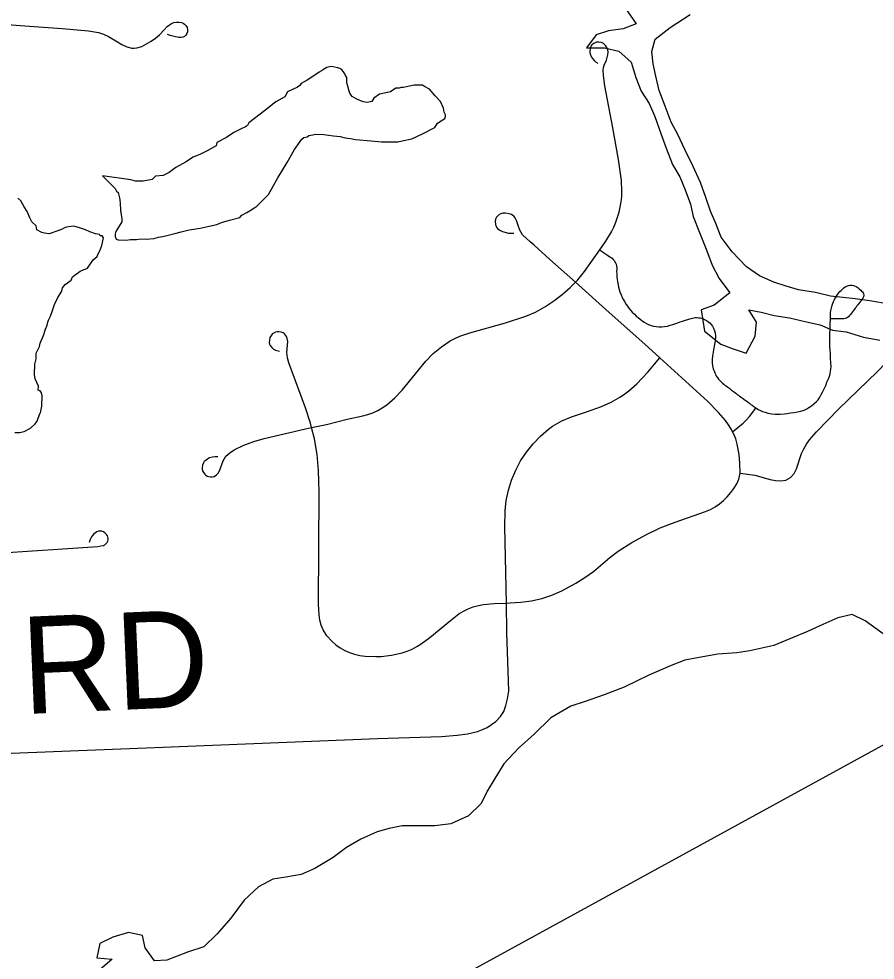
# Model space of a CAD drawing. Extents: x 0 to 34, y 0 to 22.
# Drawn here: x 6.2117 to 6.4623, y 19.1628 to 19.4382 of the extents above; entities that cross this region are included whole.
import ezdxf

# ---------------------------------------------------------------- set-up
doc = ezdxf.new("R2010")
doc.units = 0
for name, color, linetype in [('GM_X_Corporation', 7, 'Continuous'), ('GM_X_Minor_River', 7, 'Continuous'), ('GM_X_Township_Road', 7, 'Continuous'), ('GM_X_Township_Road_Text', 7, 'Continuous')]:
    doc.layers.add(name, color=color, linetype=linetype)

msp = doc.modelspace()

# ---------------------------------------------------------------- linework, layer by layer
at = {"layer": 'GM_X_Corporation'}
msp.add_lwpolyline([(6.02093, 18.98289), (6.47248, 19.23007), (6.55287, 19.2304), (6.5506, 19.34193), (6.52687, 19.36184), (6.5229, 19.4692), (6.42525, 19.4768), (6.41702, 19.54004), (6.41272, 19.59919), (6.66443, 19.85526), (6.74265, 19.90025)], dxfattribs=at)
at = {"layer": 'GM_X_Minor_River'}
for points in [[(6.38968, 19.44059), (6.39236, 19.4368), (6.38857, 19.43526), (6.38421, 19.43467), (6.38061, 19.43351), (6.37778, 19.4297), (6.38309, 19.42972), (6.38727, 19.42879), (6.3909, 19.42558), (6.39225, 19.42102), (6.39379, 19.41704), (6.39609, 19.41343), (6.39781, 19.40964), (6.39955, 19.40471), (6.40109, 19.40034), (6.40301, 19.3956), (6.40512, 19.392), (6.40665, 19.3882), (6.4082, 19.38403), (6.40897, 19.38042), (6.4109, 19.37568), (6.41301, 19.37036), (6.41455, 19.36619), (6.41666, 19.36221), (6.41972, 19.35804), (6.41518, 19.35441), (6.41139, 19.35306), (6.41237, 19.34679), (6.41714, 19.34301), (6.42075, 19.3417), (6.42455, 19.34039), (6.42719, 19.34534), (6.42755, 19.34952), (6.42525, 19.35312), (6.42886, 19.35238), (6.43266, 19.35145), (6.43722, 19.35071), (6.44216, 19.34959), (6.44615, 19.34866), (6.44977, 19.34716), (6.45376, 19.34661), (6.45889, 19.34511), (6.46364, 19.34418)], [(6.46567, 19.35484), (6.4613, 19.35558), (6.45636, 19.35631), (6.44915, 19.35704), (6.44477, 19.35816), (6.43984, 19.3589), (6.43622, 19.36002), (6.43261, 19.36114), (6.42843, 19.36302), (6.42461, 19.36567), (6.42042, 19.37002), (6.41717, 19.37438), (6.41563, 19.37836), (6.41409, 19.38196), (6.41274, 19.38595), (6.4112, 19.39032), (6.4089, 19.39525), (6.40659, 19.39999), (6.40448, 19.40435), (6.40257, 19.40795), (6.40083, 19.4127), (6.3991, 19.41725), (6.39813, 19.42143), (6.39735, 19.42504), (6.39696, 19.42865), (6.39789, 19.43226), (6.40223, 19.43571), (6.4081, 19.43953)], [(6.30729, 19.4216), (6.30711, 19.42217), (6.30673, 19.42275), (6.30617, 19.42332), (6.30561, 19.42371), (6.30504, 19.42391), (6.30316, 19.42432), (6.30258, 19.42413), (6.30182, 19.42396), (6.30087, 19.4234), (6.30029, 19.42303), (6.29953, 19.42266), (6.298, 19.42154), (6.29608, 19.42024), (6.29436, 19.41931), (6.29397, 19.41875), (6.29321, 19.41819), (6.29034, 19.4169), (6.28956, 19.41539), (6.28689, 19.41391), (6.28363, 19.4113), (6.27902, 19.40775), (6.27863, 19.407), (6.27806, 19.40663), (6.27672, 19.40607), (6.27462, 19.40497), (6.27251, 19.40348), (6.26965, 19.402), (6.26945, 19.40105), (6.26677, 19.39957), (6.26486, 19.39864), (6.26276, 19.39773), (6.26046, 19.39624), (6.2576, 19.39476), (6.25568, 19.39327), (6.25454, 19.39271), (6.25396, 19.39234), (6.25168, 19.39218), (6.25072, 19.39125), (6.24806, 19.39071), (6.24635, 19.39074), (6.24579, 19.39075), (6.24446, 19.39115), (6.23622, 19.39233)], [(6.23622, 19.39233), (6.23988, 19.38855), (6.24024, 19.38779), (6.24081, 19.3874), (6.24116, 19.38587), (6.24133, 19.38435), (6.24149, 19.38207), (6.24183, 19.37979), (6.24182, 19.37884), (6.24007, 19.37601), (6.23987, 19.37526), (6.23986, 19.3745), (6.24023, 19.37373), (6.24079, 19.37354), (6.24307, 19.3735), (6.2444, 19.37367), (6.2461, 19.37365), (6.24743, 19.37382), (6.24895, 19.3738), (6.25123, 19.37396), (6.25256, 19.37432), (6.2537, 19.37449), (6.25503, 19.37485), (6.25731, 19.37539), (6.25922, 19.37593), (6.2615, 19.37647), (6.26473, 19.377), (6.26739, 19.37753), (6.26968, 19.37806), (6.27101, 19.37862), (6.2733, 19.37934), (6.27634, 19.38006), (6.27692, 19.38081), (6.27845, 19.38155), (6.27941, 19.38211), (6.28075, 19.38304), (6.28132, 19.38341), (6.28478, 19.38678), (6.28751, 19.39168), (6.29023, 19.3962), (6.29237, 19.39997), (6.2945, 19.40298), (6.29508, 19.40354), (6.29603, 19.40371), (6.2966, 19.40409), (6.29774, 19.40426), (6.2985, 19.40444), (6.30097, 19.4044), (6.30229, 19.4042), (6.3038, 19.40398), (6.3057, 19.40377), (6.30721, 19.40337), (6.30872, 19.40316), (6.31024, 19.40294), (6.31478, 19.4025), (6.31781, 19.40227), (6.32255, 19.4022), (6.32388, 19.40256), (6.32673, 19.40309), (6.32979, 19.40457), (6.33342, 19.40642), (6.3342, 19.40773), (6.3363, 19.40903), (6.3365, 19.4096), (6.33651, 19.41017), (6.33614, 19.41094), (6.33597, 19.41208), (6.33505, 19.41399), (6.33355, 19.41572), (6.33188, 19.41764), (6.33037, 19.41843), (6.32981, 19.41881), (6.32734, 19.41885), (6.32601, 19.41849), (6.3243, 19.41813), (6.32354, 19.41814), (6.32297, 19.41796), (6.32202, 19.41797), (6.32049, 19.41685), (6.31725, 19.41614), (6.31553, 19.41502), (6.31495, 19.41408), (6.31362, 19.41372), (6.31248, 19.41393), (6.3106, 19.41471), (6.30928, 19.41549), (6.30891, 19.41588), (6.30854, 19.41645), (6.30836, 19.41703), (6.308, 19.41855), (6.30764, 19.4195), (6.30766, 19.42102), (6.30729, 19.4216)], [(6.21058, 19.31717), (6.21191, 19.31716), (6.21324, 19.31752), (6.21515, 19.31844), (6.21649, 19.31975), (6.21707, 19.3205), (6.21786, 19.32277), (6.21806, 19.32296), (6.21846, 19.32485), (6.21851, 19.32789), (6.21833, 19.32884), (6.21796, 19.32941), (6.2174, 19.32961), (6.21741, 19.33075), (6.2165, 19.33285), (6.21633, 19.33419), (6.21637, 19.33722), (6.21677, 19.33874), (6.2168, 19.34045), (6.21777, 19.34233), (6.21798, 19.34328), (6.21896, 19.34554), (6.21955, 19.34743), (6.21995, 19.34857), (6.22015, 19.34952), (6.22035, 19.35008), (6.22094, 19.35121), (6.22153, 19.35291), (6.22212, 19.35461), (6.2231, 19.35669), (6.22427, 19.35857), (6.22447, 19.35952), (6.22524, 19.36046), (6.22697, 19.36176), (6.22736, 19.36271), (6.22966, 19.36439), (6.23176, 19.3653), (6.2335, 19.36775), (6.23465, 19.36868), (6.23485, 19.36925), (6.23544, 19.37038), (6.23603, 19.37189), (6.23644, 19.37417), (6.23607, 19.37474), (6.2355, 19.37475), (6.23532, 19.37513), (6.23418, 19.37534), (6.23248, 19.37593), (6.23117, 19.37652), (6.22947, 19.37711), (6.22777, 19.37752), (6.22625, 19.37735), (6.2253, 19.37717), (6.22415, 19.37662), (6.22282, 19.37607), (6.22053, 19.37534), (6.21921, 19.37555), (6.21845, 19.37575), (6.21695, 19.37653), (6.21677, 19.37767), (6.21546, 19.37883), (6.21491, 19.37998), (6.21418, 19.38189), (6.21325, 19.38323), (6.21233, 19.38495), (6.21139, 19.38572)], [(6.46465, 19.25827), (6.45931, 19.26205), (6.45551, 19.26393), (6.45134, 19.26296), (6.44698, 19.26104), (6.44244, 19.25893), (6.43732, 19.25681), (6.43259, 19.25489), (6.42557, 19.25333), (6.42178, 19.25275), (6.41627, 19.25234), (6.41077, 19.25136), (6.4066, 19.25058), (6.40262, 19.24904), (6.39599, 19.24616), (6.3888, 19.24271), (6.38292, 19.2404), (6.37743, 19.23847), (6.37326, 19.23712), (6.36739, 19.23367), (6.36248, 19.2289), (6.35795, 19.22488), (6.3536, 19.2203), (6.35097, 19.21592), (6.34871, 19.21229), (6.34702, 19.20868), (6.34324, 19.20505), (6.33813, 19.20274), (6.33338, 19.20215), (6.32389, 19.2021), (6.3201, 19.20132), (6.3165, 19.20036), (6.31176, 19.19824), (6.3076, 19.19575), (6.30363, 19.19288), (6.29833, 19.18963), (6.29435, 19.1879), (6.2898, 19.18712), (6.28601, 19.18653), (6.28184, 19.18423), (6.27768, 19.18041), (6.27373, 19.17507), (6.26976, 19.17049), (6.2658, 19.16667), (6.26106, 19.16512), (6.25499, 19.16281), (6.25139, 19.16261), (6.24871, 19.1664), (6.24793, 19.17), (6.24375, 19.17093), (6.2392, 19.16958), (6.23542, 19.16766), (6.23449, 19.16348), (6.23905, 19.16312), (6.23546, 19.16006)], [(6.46465, 19.25827), (6.45931, 19.26205), (6.45551, 19.26393), (6.45134, 19.26296), (6.44698, 19.26104), (6.44244, 19.25893), (6.43732, 19.25681), (6.43259, 19.25489), (6.42557, 19.25333), (6.42178, 19.25275), (6.41627, 19.25234), (6.41077, 19.25136), (6.4066, 19.25058), (6.40262, 19.24904), (6.39599, 19.24616), (6.3888, 19.24271), (6.38292, 19.2404), (6.37743, 19.23847), (6.37326, 19.23712), (6.36739, 19.23367), (6.36248, 19.2289), (6.35795, 19.22488), (6.3536, 19.2203), (6.35097, 19.21592), (6.34871, 19.21229), (6.34702, 19.20868), (6.34324, 19.20505), (6.33813, 19.20274), (6.33338, 19.20215), (6.32389, 19.2021), (6.3201, 19.20132), (6.3165, 19.20036), (6.31176, 19.19824), (6.3076, 19.19575), (6.30363, 19.19288), (6.29833, 19.18963), (6.29435, 19.1879), (6.2898, 19.18712), (6.28601, 19.18653), (6.28184, 19.18423), (6.27768, 19.18041), (6.27373, 19.17507), (6.26976, 19.17049), (6.2658, 19.16667), (6.26106, 19.16512), (6.25499, 19.16281), (6.25139, 19.16261), (6.24871, 19.1664), (6.24793, 19.17), (6.24375, 19.17093), (6.2392, 19.16958), (6.23542, 19.16766), (6.23449, 19.16348), (6.23905, 19.16312), (6.23546, 19.16006)]]:
    msp.add_lwpolyline(points, dxfattribs=at)
at = {"layer": 'GM_X_Township_Road'}
for points in [[(6.2059, 19.43679), (6.21206, 19.43628), (6.2244, 19.43541), (6.23204, 19.43473), (6.23502, 19.43424), (6.23649, 19.43374), (6.23789, 19.43309), (6.24055, 19.43151), (6.24188, 19.43067), (6.24328, 19.42998), (6.24474, 19.42961), (6.24543, 19.42959), (6.24623, 19.4297), (6.24766, 19.43017), (6.24905, 19.43087), (6.2504, 19.43166), (6.25167, 19.43255), (6.25286, 19.43354), (6.2542, 19.43496), (6.25512, 19.43596), (6.25574, 19.43648), (6.25636, 19.43684), (6.25708, 19.43712), (6.25788, 19.43725), (6.2585, 19.43725), (6.25925, 19.43712), (6.25974, 19.43692), (6.26018, 19.43663), (6.26062, 19.43619), (6.26093, 19.43573), (6.26108, 19.43514), (6.26106, 19.43439), (6.26088, 19.43392), (6.26054, 19.43343), (6.26018, 19.43307), (6.25974, 19.43284), (6.2592, 19.43274), (6.25855, 19.43271), (6.2575, 19.43292), (6.25598, 19.43333), (6.25518, 19.43367)], [(6.38167, 19.37065), (6.38346, 19.37321), (6.38508, 19.37587), (6.38579, 19.37726), (6.3864, 19.37869), (6.38734, 19.38166), (6.38795, 19.38472), (6.38812, 19.38627), (6.38818, 19.38783), (6.38804, 19.39094), (6.38713, 19.39711), (6.38551, 19.40633), (6.38319, 19.41862), (6.38273, 19.42168), (6.38268, 19.42321), (6.38277, 19.42398), (6.38296, 19.42471), (6.38363, 19.42614), (6.38388, 19.42692), (6.38408, 19.42766), (6.38414, 19.42847), (6.38403, 19.42916), (6.38379, 19.42986), (6.38338, 19.43046), (6.38277, 19.43102), (6.38221, 19.43128), (6.38142, 19.4314), (6.3807, 19.43135), (6.37994, 19.43102), (6.37938, 19.43059), (6.37909, 19.43019), (6.37892, 19.42976), (6.37876, 19.42897), (6.37878, 19.42836), (6.37892, 19.42768), (6.37923, 19.42705), (6.37953, 19.42657), (6.38007, 19.426), (6.38048, 19.42564), (6.38109, 19.42526)], [(6.37457, 19.36117), (6.36711, 19.3678), (6.36253, 19.37197), (6.36134, 19.37296), (6.35909, 19.37507), (6.35864, 19.37573), (6.35831, 19.37634), (6.35777, 19.37777), (6.35733, 19.37925), (6.35697, 19.37998), (6.35652, 19.38048), (6.35584, 19.38096), (6.35517, 19.38118), (6.35414, 19.38138), (6.35336, 19.38133), (6.35276, 19.38118), (6.35226, 19.38096), (6.35183, 19.38063), (6.35146, 19.38023), (6.35118, 19.37963), (6.35108, 19.37888), (6.35118, 19.37803), (6.35151, 19.37725), (6.35178, 19.3769), (6.35216, 19.37655), (6.35261, 19.37625), (6.35321, 19.376), (6.35494, 19.37553), (6.35584, 19.37547), (6.35649, 19.37555)], [(6.37457, 19.36117), (6.37523, 19.36185), (6.3772, 19.36426), (6.38167, 19.37065)], [(6.38167, 19.37065), (6.38218, 19.37029), (6.3831, 19.36965), (6.38393, 19.3691), (6.38463, 19.36862), (6.38497, 19.36839), (6.3853, 19.36815), (6.38563, 19.3678), (6.38589, 19.36752), (6.38629, 19.36682), (6.38647, 19.3664), (6.38661, 19.36583), (6.38665, 19.36539), (6.38664, 19.36486), (6.38662, 19.36437), (6.38663, 19.36365), (6.38666, 19.36284), (6.38676, 19.36193), (6.38683, 19.36139), (6.38703, 19.3604), (6.38719, 19.35972), (6.38738, 19.35904), (6.38759, 19.35838), (6.38794, 19.35747), (6.38827, 19.35673), (6.38863, 19.356), (6.38894, 19.35549), (6.38941, 19.35467), (6.38976, 19.35416), (6.39021, 19.35356), (6.39065, 19.35299), (6.39116, 19.35243), (6.3918, 19.35177), (6.39236, 19.35124), (6.39289, 19.35079), (6.3935, 19.35031), (6.39395, 19.34998), (6.39465, 19.34951), (6.39533, 19.34911), (6.39594, 19.34881), (6.39668, 19.34852), (6.39737, 19.34833), (6.39814, 19.34818), (6.399, 19.34811), (6.39984, 19.34808), (6.40063, 19.34818), (6.40145, 19.34832), (6.40224, 19.34856), (6.40302, 19.34881), (6.40369, 19.34903), (6.40425, 19.34922), (6.40522, 19.34955), (6.40585, 19.34975), (6.40643, 19.34995), (6.40708, 19.35017), (6.40747, 19.35029), (6.40805, 19.35049), (6.4084, 19.35059), (6.40922, 19.35077), (6.40961, 19.35081), (6.41, 19.35083), (6.41059, 19.35078), (6.4111, 19.3507), (6.4118, 19.35051), (6.41232, 19.3503), (6.41288, 19.34999), (6.41325, 19.34975), (6.41359, 19.34949), (6.41396, 19.34915), (6.41427, 19.34881), (6.41462, 19.34829), (6.41496, 19.34775), (6.41526, 19.34698), (6.41542, 19.34639), (6.41548, 19.34602), (6.41553, 19.34565), (6.41554, 19.34525), (6.41555, 19.34485), (6.41549, 19.34444), (6.41541, 19.34387), (6.41526, 19.34308), (6.41516, 19.34239), (6.41507, 19.34187), (6.41499, 19.34139), (6.41487, 19.34072), (6.41478, 19.34013), (6.41471, 19.33972), (6.41466, 19.33935), (6.4146, 19.33884), (6.41458, 19.33839), (6.41458, 19.33807), (6.4146, 19.33746), (6.41468, 19.33684), (6.41478, 19.33633), (6.4149, 19.3358), (6.41502, 19.33542), (6.41522, 19.33491), (6.41534, 19.33461), (6.41551, 19.33424), (6.41568, 19.3339), (6.41594, 19.3335), (6.41614, 19.33324), (6.41644, 19.3328), (6.41667, 19.33252), (6.41696, 19.33223), (6.41729, 19.33188), (6.41757, 19.33164), (6.41796, 19.33132), (6.41838, 19.33099), (6.41867, 19.3308), (6.41914, 19.33044), (6.41971, 19.33002), (6.42027, 19.3296), (6.42056, 19.32939), (6.42107, 19.329), (6.42153, 19.32866), (6.42193, 19.32835), (6.42227, 19.32811), (6.42261, 19.32787), (6.42301, 19.32757), (6.42334, 19.32732), (6.42381, 19.32696), (6.42423, 19.32667), (6.4247, 19.32633), (6.42517, 19.32597), (6.42546, 19.32573), (6.42589, 19.32543), (6.42623, 19.32516), (6.42676, 19.32479), (6.42736, 19.32436)], [(6.29737, 19.31863), (6.30173, 19.31954), (6.30775, 19.32111), (6.31233, 19.32204), (6.31384, 19.32244), (6.31531, 19.32296), (6.31671, 19.32362), (6.31805, 19.32442), (6.31933, 19.32531), (6.32169, 19.32734), (6.32385, 19.3296), (6.33079, 19.33802), (6.33296, 19.34026), (6.33536, 19.34225), (6.33795, 19.34399), (6.33931, 19.34474), (6.34073, 19.34538), (6.34369, 19.34637), (6.35413, 19.34928), (6.36004, 19.35119), (6.3629, 19.35243), (6.36562, 19.35396), (6.36822, 19.35567), (6.3707, 19.35756), (6.37305, 19.35962), (6.37457, 19.36117)], [(6.39926, 19.33906), (6.39488, 19.34307), (6.38447, 19.35234), (6.37457, 19.36117)], [(6.44916, 19.35043), (6.44918, 19.35127), (6.44924, 19.3523), (6.4494, 19.35326), (6.44959, 19.35409), (6.44979, 19.35475), (6.44998, 19.35527), (6.45016, 19.35569), (6.45039, 19.35613), (6.45065, 19.35663), (6.45094, 19.35709), (6.45127, 19.35756), (6.45165, 19.35804), (6.45197, 19.35842), (6.45231, 19.35878), (6.45274, 19.35917), (6.45314, 19.35954), (6.45348, 19.35977), (6.4538, 19.35995), (6.45412, 19.3601), (6.45445, 19.36019), (6.45495, 19.36028), (6.45552, 19.36026), (6.45588, 19.3602), (6.45625, 19.36009), (6.4567, 19.35991), (6.457, 19.35973), (6.45727, 19.35952), (6.45758, 19.35924), (6.45802, 19.35882), (6.4583, 19.35856), (6.45853, 19.35833), (6.45875, 19.35808), (6.45889, 19.3578), (6.45897, 19.35733), (6.45889, 19.35688), (6.45867, 19.35651), (6.45837, 19.35611), (6.45807, 19.35572), (6.45779, 19.35536), (6.45749, 19.35496), (6.45715, 19.35452), (6.45694, 19.35425), (6.45668, 19.3539), (6.45642, 19.35357), (6.45617, 19.35325), (6.45591, 19.3529), (6.4556, 19.3525), (6.45531, 19.35211), (6.455, 19.3517), (6.45477, 19.35141), (6.45441, 19.35101), (6.45415, 19.35081), (6.45388, 19.35066), (6.45348, 19.35052), (6.45312, 19.35046), (6.45273, 19.35046), (6.45221, 19.35045), (6.45176, 19.35045), (6.45123, 19.35045), (6.45081, 19.35044), (6.45016, 19.35043), (6.44954, 19.35043), (6.44916, 19.35043)], [(6.42736, 19.32436), (6.42804, 19.32396), (6.42867, 19.32366), (6.42931, 19.32337), (6.43006, 19.3231), (6.43083, 19.32286), (6.43206, 19.32265), (6.43299, 19.32256), (6.43376, 19.32255), (6.43446, 19.32256), (6.43561, 19.32265), (6.43653, 19.32276), (6.43747, 19.3229), (6.43843, 19.32301), (6.43958, 19.32324), (6.44051, 19.32344), (6.44153, 19.32375), (6.44229, 19.32413), (6.44289, 19.32451), (6.44364, 19.32497), (6.44436, 19.32558), (6.44508, 19.32624), (6.44554, 19.32679), (6.44605, 19.32755), (6.44647, 19.32831), (6.44682, 19.32895), (6.44714, 19.32959), (6.44749, 19.33034), (6.44778, 19.33098), (6.44816, 19.33187), (6.44851, 19.33267), (6.44879, 19.33342), (6.44907, 19.33433), (6.44923, 19.33511), (6.44932, 19.33573), (6.44936, 19.33647), (6.4493, 19.33745), (6.44922, 19.33899), (6.44917, 19.34023), (6.44909, 19.34134), (6.44902, 19.34222), (6.44897, 19.34316), (6.44897, 19.3448), (6.44901, 19.34609), (6.4491, 19.34751), (6.44909, 19.34825), (6.44907, 19.34876), (6.44916, 19.35043)], [(6.29737, 19.31863), (6.29705, 19.31993), (6.29562, 19.3244), (6.29069, 19.33757), (6.29029, 19.33906), (6.29014, 19.3406), (6.29038, 19.34378), (6.29022, 19.34467), (6.29002, 19.34525), (6.28957, 19.34593), (6.28934, 19.34614), (6.28908, 19.34631), (6.28845, 19.34655), (6.2878, 19.34667), (6.28727, 19.34665), (6.28678, 19.34653), (6.28611, 19.34617), (6.28585, 19.34595), (6.2856, 19.34565), (6.28519, 19.34498), (6.28502, 19.34423), (6.28499, 19.34348), (6.28507, 19.34307), (6.28525, 19.34265), (6.28569, 19.34205), (6.2862, 19.34158), (6.28676, 19.34131), (6.28799, 19.341)], [(6.35435, 19.2673), (6.35393, 19.2896), (6.35397, 19.29424), (6.35427, 19.29732), (6.35493, 19.30034), (6.35589, 19.30328), (6.35708, 19.30614), (6.35853, 19.30887), (6.36022, 19.31146), (6.36216, 19.31386), (6.36432, 19.31608), (6.36665, 19.31812), (6.36789, 19.31904), (6.3692, 19.31985), (6.37058, 19.32057), (6.37343, 19.32175), (6.37783, 19.32324), (6.38219, 19.32481), (6.38502, 19.32608), (6.38772, 19.32759), (6.38899, 19.32846), (6.39022, 19.3294), (6.39252, 19.33147), (6.39573, 19.33482), (6.3977, 19.3372), (6.39926, 19.33906)], [(6.42055, 19.3174), (6.42019, 19.31811), (6.41938, 19.31942), (6.41847, 19.32068), (6.41645, 19.32303), (6.41316, 19.32631), (6.39926, 19.33906)], [(6.42275, 19.30527), (6.42701, 19.30473), (6.43158, 19.30348), (6.43312, 19.30315), (6.43465, 19.30302), (6.43617, 19.30328), (6.43751, 19.30407), (6.43856, 19.3052), (6.43929, 19.30656), (6.44074, 19.31101), (6.44137, 19.31243), (6.44214, 19.31378), (6.44304, 19.31505), (6.44506, 19.31741), (6.4516, 19.32409), (6.4628, 19.33491), (6.46555, 19.33779)], [(6.42055, 19.3174), (6.42365, 19.31991), (6.42451, 19.32083), (6.42547, 19.32185), (6.42672, 19.3235), (6.42736, 19.32436)], [(6.26989, 19.31003), (6.26909, 19.31004), (6.26833, 19.30996), (6.2675, 19.30975), (6.26686, 19.30942), (6.26618, 19.30894), (6.26595, 19.30867), (6.26569, 19.30827), (6.26545, 19.30761), (6.26532, 19.30688), (6.26534, 19.30648), (6.26547, 19.30595), (6.26571, 19.30545), (6.26609, 19.30496), (6.26642, 19.30467), (6.26681, 19.30446), (6.26728, 19.30427), (6.26774, 19.3042), (6.26827, 19.30422), (6.26885, 19.30436), (6.26957, 19.3048), (6.27, 19.30526), (6.27042, 19.30597), (6.27148, 19.30895), (6.2723, 19.31023), (6.2734, 19.31127), (6.27473, 19.31209), (6.27755, 19.31345), (6.28046, 19.31457), (6.28345, 19.31545), (6.29561, 19.31824), (6.29737, 19.31863)], [(6.30326, 19.25613), (6.30182, 19.25771), (6.30077, 19.25946), (6.3002, 19.26082), (6.29976, 19.26232), (6.29953, 19.26386), (6.29942, 19.26698), (6.29954, 19.29987), (6.2994, 19.30609), (6.29895, 19.31075), (6.29817, 19.31537), (6.29737, 19.31863)], [(6.42275, 19.30527), (6.42269, 19.30819), (6.42249, 19.31077), (6.4219, 19.31381), (6.42146, 19.31529), (6.42089, 19.31673), (6.42055, 19.3174)], [(6.35435, 19.2673), (6.35549, 19.26733), (6.3586, 19.26753), (6.36169, 19.26796), (6.36474, 19.26864), (6.36769, 19.26963), (6.37054, 19.2709), (6.37469, 19.2731), (6.37735, 19.27473), (6.37988, 19.27654), (6.38465, 19.28058), (6.3871, 19.28251), (6.39106, 19.285), (6.39516, 19.28727), (6.39939, 19.28926), (6.40375, 19.29098), (6.41261, 19.29403), (6.41404, 19.29466), (6.4154, 19.2954), (6.41668, 19.29629), (6.41787, 19.2973), (6.41898, 19.2984), (6.41999, 19.29959), (6.42091, 19.30085), (6.42175, 19.30217), (6.42234, 19.30352), (6.42275, 19.30527)], [(6.20532, 19.28191), (6.23481, 19.28379), (6.23574, 19.28399), (6.23644, 19.28417), (6.23686, 19.28436), (6.23728, 19.28469), (6.23753, 19.285), (6.2377, 19.28537), (6.23782, 19.28582), (6.23785, 19.28621), (6.23779, 19.28656), (6.23766, 19.28692), (6.2374, 19.28735), (6.2369, 19.28784), (6.23644, 19.28815), (6.23602, 19.2883), (6.23551, 19.28836), (6.23498, 19.28829), (6.23453, 19.28812), (6.23414, 19.28788), (6.23366, 19.28753), (6.23324, 19.28704), (6.23298, 19.2867), (6.23276, 19.2863), (6.23254, 19.28588), (6.23235, 19.28534), (6.23228, 19.28499)], [(6.30326, 19.25613), (6.30441, 19.25509), (6.30568, 19.25418), (6.30704, 19.25341), (6.30847, 19.25278), (6.30995, 19.2523), (6.31148, 19.25196), (6.31302, 19.25174), (6.31614, 19.25162), (6.3177, 19.25169), (6.32079, 19.25209), (6.32385, 19.2527), (6.32534, 19.25319), (6.32676, 19.25382), (6.32813, 19.25457), (6.32945, 19.2554), (6.33196, 19.25726), (6.338, 19.2622), (6.34049, 19.2641), (6.34181, 19.26493), (6.3432, 19.26562), (6.34466, 19.26618), (6.34616, 19.26659), (6.3477, 19.2669), (6.3508, 19.26721), (6.35435, 19.2673)], [(6.35503, 19.24163), (6.3545, 19.25867), (6.35435, 19.2673)], [(6.12002, 19.21982), (6.13048, 19.22022), (6.15686, 19.22138), (6.18014, 19.22223), (6.22669, 19.2241), (6.25151, 19.22507), (6.31669, 19.22768), (6.33533, 19.22827), (6.33994, 19.2286), (6.34298, 19.22905), (6.34594, 19.22976), (6.34736, 19.23027), (6.34872, 19.23091), (6.35125, 19.23266), (6.35259, 19.23406), (6.35357, 19.23553), (6.35424, 19.23729), (6.35473, 19.23925), (6.35503, 19.24163)]]:
    msp.add_lwpolyline(points, dxfattribs=at)

# ---------------------------------------------------------------- texts
at = {"layer": 'GM_X_Township_Road_Text'}
msp.add_text('RD', height=0.028409, rotation=2.4692, dxfattribs=at).set_placement((6.21303, 19.2348))

doc.saveas('drawing.dxf')
